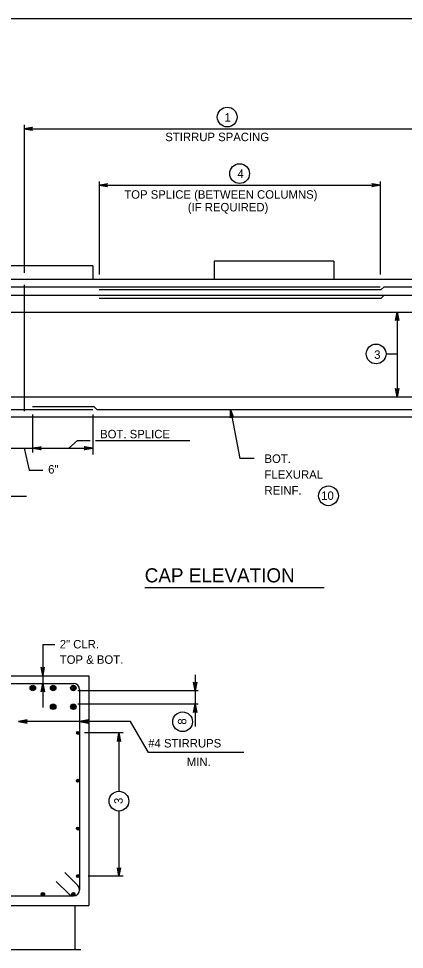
# Model space of a CAD drawing. Extents: x 646165 to 651486, y 296916 to 299292.
# Drawn here: x 648594.6 to 648731.2, y 298353.5 to 298683.3 of the extents above; entities that cross this region are included whole.
import ezdxf

# ---------------------------------------------------------------- set-up
doc = ezdxf.new("R2010")
doc.units = 0
for name, color, linetype in [('2', 7, 'Continuous'), ('51', 7, 'Continuous'), ('52', 7, 'Continuous'), ('53', 7, 'Continuous'), ('54', 7, 'Continuous')]:
    doc.layers.add(name, color=color, linetype=linetype)

msp = doc.modelspace()

# ---------------------------------------------------------------- linework, layer by layer
at = {"layer": '2'}
msp.add_line((648147.59, 298683.25), (648933.59, 298683.25), dxfattribs=at)
at = {"layer": '51'}
for p, q in [((648620.84, 298595.61), (648578.44, 298595.61)), ((648620.84, 298595.61), (648620.84, 298590.91)), ((648663.85, 298597.32), (648663.85, 298590.91)), ((648706.25, 298597.32), (648663.85, 298597.32)), ((648706.25, 298597.32), (648706.25, 298590.91)), ((648477.66, 298590.91), (648896.65, 298590.91)), ((648553.98, 298542.11), (648896.65, 298542.11)), ((648548.38, 298450.37), (648619.5, 298450.37)), ((648619.5, 298450.37), (648619.5, 298369.03)), ((648548.38, 298369.03), (648619.5, 298369.03)), ((648614.5, 298369.03), (648614.5, 298353.45))]:
    msp.add_line(p, q, dxfattribs=at)
at = {"layer": '52'}
for p, q in [((648596.54, 298645.56), (648596.54, 298593.17)), ((648596.54, 298644.24), (648749.18, 298644.24)), ((648623.06, 298625.56), (648623.06, 298592.54)), ((648722.66, 298625.56), (648722.66, 298592.54)), ((648623.06, 298624.24), (648722.66, 298624.24)), ((648728.65, 298579.23), (648728.65, 298549.23)), ((648724.72, 298564.43), (648728.65, 298564.43)), ((648599.54, 298542.99), (648599.54, 298529.5)), ((648620.82, 298542.99), (648620.82, 298528.78)), ((648669.58, 298544.79), (648672.94, 298527.39)), ((648615.48, 298533.78), (648612.41, 298531.01)), ((648615.48, 298533.78), (648619.94, 298533.78)), ((648621.81, 298533.78), (648655.22, 298533.78)), ((648588.01, 298531.01), (648620.82, 298531.01)), ((648596.55, 298531.01), (648598.25, 298523.3)), ((648678.05, 298527.39), (648672.94, 298527.39)), ((648598.25, 298523.3), (648603.18, 298523.3)), ((648578.76, 298514.09), (648597.33, 298514.09)), ((648603.16, 298461.53), (648603.16, 298439.17)), ((648603.16, 298461.53), (648607.43, 298461.53)), ((648657.14, 298450.73), (648657.14, 298432.38)), ((648658.15, 298445.1), (648615.57, 298445.1)), ((648658.15, 298440.37), (648615.57, 298440.37)), ((648634.21, 298434.21), (648594.57, 298434.21)), ((648640.56, 298423.21), (648634.21, 298434.21)), ((648631.66, 298430.15), (648617.93, 298430.15)), ((648630.11, 298430.15), (648630.11, 298409.48)), ((648674.31, 298423.21), (648640.56, 298423.21)), ((648630.11, 298402.48), (648630.11, 298379.4)), ((648631.66, 298379.4), (648619.24, 298379.4)), ((648586.61, 298353.45), (648616.57, 298353.45))]:
    msp.add_line(p, q, dxfattribs=at)
for points in [[(648596.54, 298644.24), (648599.53, 298644.8), (648599.41, 298644.72), (648599.3, 298644.64), (648599.24, 298644.54), (648599.18, 298644.44), (648599.16, 298644.34), (648599.14, 298644.24), (648599.16, 298644.14), (648599.18, 298644.04), (648599.24, 298643.94), (648599.3, 298643.84), (648599.41, 298643.76), (648599.53, 298643.68), (648596.54, 298644.24), (648599.41, 298643.76), (648599.3, 298643.84), (648596.54, 298644.24), (648599.24, 298643.94), (648599.18, 298644.04), (648596.54, 298644.24), (648599.16, 298644.14), (648599.14, 298644.24), (648596.54, 298644.24), (648599.16, 298644.34), (648599.18, 298644.44), (648596.54, 298644.24), (648599.24, 298644.54), (648599.3, 298644.64), (648596.54, 298644.24), (648599.41, 298644.72)], [(648623.06, 298624.24), (648626.05, 298624.8), (648625.93, 298624.72), (648625.82, 298624.64), (648625.76, 298624.54), (648625.7, 298624.44), (648625.68, 298624.34), (648625.66, 298624.24), (648625.68, 298624.14), (648625.7, 298624.04), (648625.76, 298623.94), (648625.82, 298623.84), (648625.93, 298623.76), (648626.05, 298623.68), (648623.06, 298624.24), (648625.93, 298623.76), (648625.82, 298623.84), (648623.06, 298624.24), (648625.76, 298623.94), (648625.7, 298624.04), (648623.06, 298624.24), (648625.68, 298624.14), (648625.66, 298624.24), (648623.06, 298624.24), (648625.68, 298624.34), (648625.7, 298624.44), (648623.06, 298624.24), (648625.76, 298624.54), (648625.82, 298624.64), (648623.06, 298624.24), (648625.93, 298624.72)], [(648722.66, 298624.24), (648719.68, 298623.68), (648719.8, 298623.76), (648719.91, 298623.84), (648719.97, 298623.94), (648720.03, 298624.04), (648720.05, 298624.14), (648720.06, 298624.24), (648720.05, 298624.34), (648720.03, 298624.44), (648719.97, 298624.54), (648719.91, 298624.64), (648719.8, 298624.72), (648719.68, 298624.8), (648722.66, 298624.24), (648719.8, 298624.72), (648719.91, 298624.64), (648722.66, 298624.24), (648719.97, 298624.54), (648720.03, 298624.44), (648722.66, 298624.24), (648720.05, 298624.34), (648720.06, 298624.24), (648722.66, 298624.24), (648720.05, 298624.14), (648720.03, 298624.04), (648722.66, 298624.24), (648719.97, 298623.94), (648719.91, 298623.84), (648722.66, 298624.24), (648719.8, 298623.76)], [(648728.65, 298579.23), (648729.21, 298576.24), (648729.13, 298576.36), (648729.05, 298576.47), (648728.95, 298576.53), (648728.85, 298576.59), (648728.75, 298576.61), (648728.65, 298576.63), (648728.55, 298576.61), (648728.45, 298576.59), (648728.35, 298576.53), (648728.25, 298576.47), (648728.17, 298576.36), (648728.09, 298576.24), (648728.65, 298579.23), (648728.17, 298576.36), (648728.25, 298576.47), (648728.65, 298579.23), (648728.35, 298576.53), (648728.45, 298576.59), (648728.65, 298579.23), (648728.55, 298576.61), (648728.65, 298576.63), (648728.65, 298579.23), (648728.75, 298576.61), (648728.85, 298576.59), (648728.65, 298579.23), (648728.95, 298576.53), (648729.05, 298576.47), (648728.65, 298579.23), (648729.13, 298576.36)], [(648728.65, 298549.23), (648728.09, 298552.21), (648728.17, 298552.09), (648728.25, 298551.98), (648728.35, 298551.92), (648728.45, 298551.86), (648728.55, 298551.84), (648728.65, 298551.83), (648728.75, 298551.84), (648728.85, 298551.86), (648728.95, 298551.92), (648729.05, 298551.98), (648729.13, 298552.09), (648729.21, 298552.21), (648728.65, 298549.23), (648729.13, 298552.09), (648729.05, 298551.98), (648728.65, 298549.23), (648728.95, 298551.92), (648728.85, 298551.86), (648728.65, 298549.23), (648728.75, 298551.84), (648728.65, 298551.83), (648728.65, 298549.23), (648728.55, 298551.84), (648728.45, 298551.86), (648728.65, 298549.23), (648728.35, 298551.92), (648728.25, 298551.98), (648728.65, 298549.23), (648728.17, 298552.09)], [(648669.58, 298544.79), (648670.69, 298541.96), (648670.59, 298542.06), (648670.49, 298542.16), (648670.38, 298542.2), (648670.27, 298542.24), (648670.17, 298542.24), (648670.07, 298542.23), (648669.98, 298542.2), (648669.88, 298542.16), (648669.8, 298542.09), (648669.71, 298542.01), (648669.65, 298541.88), (648669.6, 298541.75), (648669.58, 298544.79), (648669.65, 298541.88), (648669.71, 298542.01), (648669.58, 298544.79), (648669.8, 298542.09), (648669.88, 298542.16), (648669.58, 298544.79), (648669.98, 298542.2), (648670.07, 298542.23), (648669.58, 298544.79), (648670.17, 298542.24), (648670.27, 298542.24), (648669.58, 298544.79), (648670.38, 298542.2), (648670.49, 298542.16), (648669.58, 298544.79), (648670.59, 298542.06)], [(648599.54, 298531.01), (648602.53, 298531.57), (648602.41, 298531.49), (648602.3, 298531.41), (648602.24, 298531.31), (648602.18, 298531.21), (648602.16, 298531.11), (648602.14, 298531.01), (648602.16, 298530.91), (648602.18, 298530.81), (648602.24, 298530.71), (648602.3, 298530.61), (648602.41, 298530.53), (648602.53, 298530.45), (648599.54, 298531.01), (648602.41, 298530.53), (648602.3, 298530.61), (648599.54, 298531.01), (648602.24, 298530.71), (648602.18, 298530.81), (648599.54, 298531.01), (648602.16, 298530.91), (648602.14, 298531.01), (648599.54, 298531.01), (648602.16, 298531.11), (648602.18, 298531.21), (648599.54, 298531.01), (648602.24, 298531.31), (648602.3, 298531.41), (648599.54, 298531.01), (648602.41, 298531.49)], [(648620.82, 298531.01), (648617.84, 298530.45), (648617.96, 298530.53), (648618.07, 298530.61), (648618.13, 298530.71), (648618.19, 298530.81), (648618.21, 298530.91), (648618.22, 298531.01), (648618.21, 298531.11), (648618.19, 298531.21), (648618.13, 298531.31), (648618.07, 298531.41), (648617.96, 298531.49), (648617.84, 298531.57), (648620.82, 298531.01), (648617.96, 298531.49), (648618.07, 298531.41), (648620.82, 298531.01), (648618.13, 298531.31), (648618.19, 298531.21), (648620.82, 298531.01), (648618.21, 298531.11), (648618.22, 298531.01), (648620.82, 298531.01), (648618.21, 298530.91), (648618.19, 298530.81), (648620.82, 298531.01), (648618.13, 298530.71), (648618.07, 298530.61), (648620.82, 298531.01), (648617.96, 298530.53)], [(648603.11, 298450.44), (648602.55, 298453.43), (648602.63, 298453.31), (648602.71, 298453.2), (648602.81, 298453.14), (648602.91, 298453.08), (648603.01, 298453.06), (648603.11, 298453.04), (648603.21, 298453.06), (648603.31, 298453.08), (648603.41, 298453.14), (648603.51, 298453.2), (648603.59, 298453.31), (648603.67, 298453.43), (648603.11, 298450.44), (648603.59, 298453.31), (648603.51, 298453.2), (648603.11, 298450.44), (648603.41, 298453.14), (648603.31, 298453.08), (648603.11, 298450.44), (648603.21, 298453.06), (648603.11, 298453.04), (648603.11, 298450.44), (648603.01, 298453.06), (648602.91, 298453.08), (648603.11, 298450.44), (648602.81, 298453.14), (648602.71, 298453.2), (648603.11, 298450.44), (648602.63, 298453.31)], [(648603.16, 298447.64), (648603.72, 298444.66), (648603.64, 298444.77), (648603.56, 298444.89), (648603.46, 298444.95), (648603.36, 298445), (648603.26, 298445.02), (648603.16, 298445.04), (648603.06, 298445.02), (648602.96, 298445), (648602.86, 298444.95), (648602.76, 298444.89), (648602.68, 298444.77), (648602.6, 298444.66), (648603.16, 298447.64), (648602.68, 298444.77), (648602.76, 298444.89), (648603.16, 298447.64), (648602.86, 298444.95), (648602.96, 298445), (648603.16, 298447.64), (648603.06, 298445.02), (648603.16, 298445.04), (648603.16, 298447.64), (648603.26, 298445.02), (648603.36, 298445), (648603.16, 298447.64), (648603.46, 298444.95), (648603.56, 298444.89), (648603.16, 298447.64), (648603.64, 298444.77)], [(648657.14, 298445.1), (648656.58, 298448.08), (648656.66, 298447.97), (648656.74, 298447.85), (648656.84, 298447.79), (648656.94, 298447.73), (648657.04, 298447.72), (648657.14, 298447.7), (648657.24, 298447.72), (648657.34, 298447.73), (648657.44, 298447.79), (648657.54, 298447.85), (648657.62, 298447.97), (648657.7, 298448.08), (648657.14, 298445.1), (648657.62, 298447.97), (648657.54, 298447.85), (648657.14, 298445.1), (648657.44, 298447.79), (648657.34, 298447.73), (648657.14, 298445.1), (648657.24, 298447.72), (648657.14, 298447.7), (648657.14, 298445.1), (648657.04, 298447.72), (648656.94, 298447.73), (648657.14, 298445.1), (648656.84, 298447.79), (648656.74, 298447.85), (648657.14, 298445.1), (648656.66, 298447.97)], [(648657.14, 298440.37), (648657.7, 298437.38), (648657.62, 298437.5), (648657.54, 298437.61), (648657.44, 298437.67), (648657.34, 298437.73), (648657.24, 298437.75), (648657.14, 298437.77), (648657.04, 298437.75), (648656.94, 298437.73), (648656.84, 298437.67), (648656.74, 298437.61), (648656.66, 298437.5), (648656.58, 298437.38), (648657.14, 298440.37), (648656.66, 298437.5), (648656.74, 298437.61), (648657.14, 298440.37), (648656.84, 298437.67), (648656.94, 298437.73), (648657.14, 298440.37), (648657.04, 298437.75), (648657.14, 298437.77), (648657.14, 298440.37), (648657.24, 298437.75), (648657.34, 298437.73), (648657.14, 298440.37), (648657.44, 298437.67), (648657.54, 298437.61), (648657.14, 298440.37), (648657.62, 298437.5)], [(648594.57, 298434.21), (648597.55, 298433.65), (648597.44, 298433.73), (648597.32, 298433.81), (648597.26, 298433.91), (648597.21, 298434.01), (648597.19, 298434.11), (648597.17, 298434.21), (648597.19, 298434.31), (648597.21, 298434.41), (648597.26, 298434.51), (648597.32, 298434.61), (648597.44, 298434.69), (648597.55, 298434.76), (648594.57, 298434.21), (648597.44, 298434.69), (648597.32, 298434.61), (648594.57, 298434.21), (648597.26, 298434.51), (648597.21, 298434.41), (648594.57, 298434.21), (648597.19, 298434.31), (648597.17, 298434.21), (648594.57, 298434.21), (648597.19, 298434.11), (648597.21, 298434.01), (648594.57, 298434.21), (648597.26, 298433.91), (648597.32, 298433.81), (648594.57, 298434.21), (648597.44, 298433.73)], [(648616.17, 298434.21), (648619.15, 298433.65), (648619.04, 298433.73), (648618.92, 298433.81), (648618.86, 298433.91), (648618.81, 298434.01), (648618.79, 298434.11), (648618.77, 298434.21), (648618.79, 298434.31), (648618.81, 298434.41), (648618.86, 298434.51), (648618.92, 298434.61), (648619.04, 298434.69), (648619.15, 298434.76), (648616.17, 298434.21), (648619.04, 298434.69), (648618.92, 298434.61), (648616.17, 298434.21), (648618.86, 298434.51), (648618.81, 298434.41), (648616.17, 298434.21), (648618.79, 298434.31), (648618.77, 298434.21), (648616.17, 298434.21), (648618.79, 298434.11), (648618.81, 298434.01), (648616.17, 298434.21), (648618.86, 298433.91), (648618.92, 298433.81), (648616.17, 298434.21), (648619.04, 298433.73)], [(648630.11, 298430.15), (648630.67, 298427.16), (648630.59, 298427.28), (648630.51, 298427.39), (648630.41, 298427.45), (648630.31, 298427.51), (648630.21, 298427.53), (648630.11, 298427.55), (648630.01, 298427.53), (648629.91, 298427.51), (648629.81, 298427.45), (648629.71, 298427.39), (648629.63, 298427.28), (648629.55, 298427.16), (648630.11, 298430.15), (648629.63, 298427.28), (648629.71, 298427.39), (648630.11, 298430.15), (648629.81, 298427.45), (648629.91, 298427.51), (648630.11, 298430.15), (648630.01, 298427.53), (648630.11, 298427.55), (648630.11, 298430.15), (648630.21, 298427.53), (648630.31, 298427.51), (648630.11, 298430.15), (648630.41, 298427.45), (648630.51, 298427.39), (648630.11, 298430.15), (648630.59, 298427.28)], [(648630.11, 298379.4), (648629.55, 298382.38), (648629.63, 298382.27), (648629.71, 298382.15), (648629.81, 298382.09), (648629.91, 298382.03), (648630.01, 298382.02), (648630.11, 298382), (648630.21, 298382.02), (648630.31, 298382.03), (648630.41, 298382.09), (648630.51, 298382.15), (648630.59, 298382.27), (648630.67, 298382.38), (648630.11, 298379.4), (648630.59, 298382.27), (648630.51, 298382.15), (648630.11, 298379.4), (648630.41, 298382.09), (648630.31, 298382.03), (648630.11, 298379.4), (648630.21, 298382.02), (648630.11, 298382), (648630.11, 298379.4), (648630.01, 298382.02), (648629.91, 298382.03), (648630.11, 298379.4), (648629.81, 298382.09), (648629.71, 298382.15), (648630.11, 298379.4), (648629.63, 298382.27)]]:
    msp.add_lwpolyline(points, dxfattribs=at)
for centre in [(648668.46, 298648.36), (648672.86, 298628.33), (648721.22, 298564.43), (648704.33, 298514.17), (648652.67, 298434.1), (648630.11, 298405.98)]:
    msp.add_circle(centre, 3.5, dxfattribs=at)
at = {"layer": '53'}
msp.add_line((648639.33, 298481.7), (648702.8, 298481.7), dxfattribs=at)
at = {"layer": '54'}
for p, q in [((648485.5, 298588.23), (648722.66, 298588.23)), ((648596.54, 298588.91), (648596.54, 298544.11)), ((648723.06, 298587.23), (648724.06, 298588.23)), ((648724.06, 298588.23), (648896.65, 298588.23)), ((648488.5, 298585.23), (648817.86, 298585.23)), ((648623.06, 298587.23), (648723.06, 298587.23)), ((648723.06, 298584.23), (648724.06, 298585.23)), ((648623.06, 298584.23), (648723.06, 298584.23)), ((648479.66, 298579.23), (648896.65, 298579.23)), ((648533.44, 298549.23), (648896.65, 298549.23)), ((648599.54, 298545.79), (648621.22, 298545.79)), ((648621.22, 298545.79), (648622.22, 298544.79)), ((648554.31, 298544.79), (648620.82, 298544.79)), ((648622.22, 298544.79), (648896.65, 298544.79)), ((648575.52, 298447.7), (648613.97, 298447.7)), ((648616.17, 298445.5), (648616.17, 298374.57)), ((648615.53, 298376.12), (648611, 298380.65)), ((648612.42, 298373.01), (648607.89, 298377.54)), ((648575.52, 298372.37), (648613.97, 298372.37))]:
    msp.add_line(p, q, dxfattribs=at)
for centre, radius in [((648599.61, 298446.07), 0.967), ((648599.61, 298446.07), 0.725), ((648599.61, 298446.07), 0.483), ((648599.61, 298446.07), 0.242), ((648606.81, 298446.07), 0.967), ((648606.81, 298446.07), 0.725), ((648606.81, 298446.07), 0.483), ((648606.81, 298446.07), 0.242), ((648613.97, 298446.07), 0.967), ((648613.97, 298446.07), 0.725), ((648613.97, 298446.07), 0.483), ((648613.97, 298446.07), 0.242), ((648606.81, 298439.4), 0.967), ((648606.81, 298439.4), 0.725), ((648606.81, 298439.4), 0.483), ((648606.81, 298439.4), 0.242), ((648613.97, 298439.4), 0.967), ((648613.97, 298439.4), 0.725), ((648613.97, 298439.4), 0.483), ((648613.97, 298439.4), 0.242), ((648615.64, 298430.15), 0.533), ((648615.64, 298430.15), 0.4), ((648615.64, 298430.15), 0.267), ((648615.64, 298430.15), 0.133), ((648615.59, 298413.21), 0.533), ((648615.59, 298413.21), 0.4), ((648615.59, 298413.21), 0.267), ((648615.59, 298413.21), 0.133), ((648615.59, 298396.28), 0.533), ((648615.59, 298396.28), 0.4), ((648615.59, 298396.28), 0.267), ((648615.59, 298396.28), 0.133), ((648615.64, 298379.4), 0.533), ((648615.64, 298379.4), 0.4), ((648615.64, 298379.4), 0.267), ((648615.64, 298379.4), 0.133), ((648603.17, 298373), 0.633), ((648603.17, 298373), 0.475), ((648603.17, 298373), 0.317), ((648603.17, 298373), 0.158), ((648613.97, 298373), 0.633), ((648613.97, 298373), 0.475), ((648613.97, 298373), 0.317), ((648613.97, 298373), 0.158)]:
    msp.add_circle(centre, radius, dxfattribs=at)
for centre, start, end in [((648613.97, 298445.5), 0, 90), ((648613.97, 298374.57), 225, 45)]:
    msp.add_arc(centre, 2.2, start, end, dxfattribs=at)

# ---------------------------------------------------------------- texts
at = {"layer": '53'}
for s, height, p in [('1', 3, (648667.5, 298646.75)), ('STIRRUP SPACING', 3, (648646.53, 298639.83)), ('4', 3, (648672.12, 298626.81)), ('TOP SPLICE (BETWEEN COLUMNS)', 3, (648632, 298619.44)), ('(IF REQUIRED)', 3, (648654.5, 298614.94)), ('3', 3, (648720.52, 298562.68)), ('BOT. SPLICE', 3, (648623.44, 298534.53)), ('BOT.', 3, (648681.67, 298525.84)), ('6"', 3, (648605.03, 298522.05)), ('FLEXURAL', 3, (648681.67, 298520.22)), ('REINF.', 3, (648681.67, 298514.59)), ('10', 3, (648701.75, 298512.72)), ('CAP ELEVATION', 5, (648639.24, 298483.49)), ('2" CLR.', 3, (648609.14, 298460.09)), ('TOP & BOT.', 3, (648609.14, 298454.64)), ('#4 STIRRUPS', 3, (648640.48, 298425)), ('MIN.', 3, (648654.14, 298418.39))]:
    msp.add_text(s, height=height, dxfattribs=at).set_placement(p)
for s, p in [('8', (648653.99, 298433.08)), ('3', (648631.44, 298404.95))]:
    msp.add_text(s, height=3, rotation=90, dxfattribs=at).set_placement(p)

doc.saveas('drawing.dxf')
